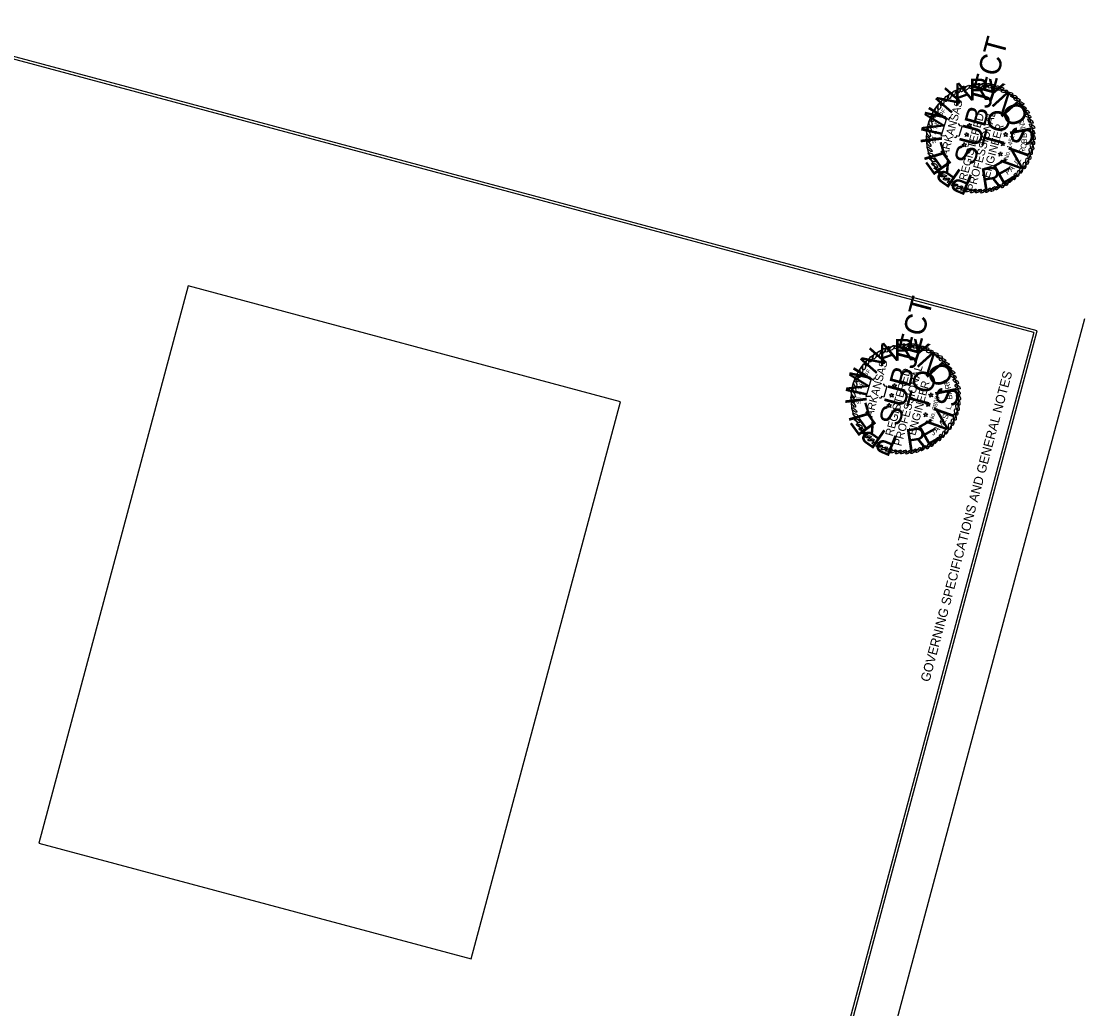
# Model space of a CAD drawing. Extents: x 1272249 to 1274802, y 195141 to 198564.
# Drawn here: x 1273878 to 1274802, y 197678 to 198536 of the extents above; entities that cross this region are included whole.
import ezdxf

# ---------------------------------------------------------------- set-up
doc = ezdxf.new("R2010")
doc.units = 0
for name, color, linetype in [('Level 61', 7, 'Continuous'), ('R_Border', 7, 'Continuous'), ('R_Border Notes', 7, 'Continuous'), ('R_Border PE', 7, 'Continuous'), ('R_Border Prem', 7, 'Continuous'), ('R_No Plot', 7, 'Continuous'), ('T_Drafting', 7, 'Continuous'), ('TXT', 7, 'Continuous')]:
    doc.layers.add(name, color=color, linetype=linetype)

msp = doc.modelspace()

# ---------------------------------------------------------------- linework, layer by layer
at = {"layer": 'Level 61'}
for points in [[(1274681.2, 198436.47), (1274677.79, 198436.3), (1274682.45, 198451.93), (1274684.26, 198450.2), (1274685.05, 198452.58), (1274685.3, 198452.35)], [(1274692.52, 198447.21), (1274693.57, 198445.53), (1274695.82, 198445.24), (1274693.01, 198435.9), (1274690.98, 198436.44), (1274690.53, 198434.75), (1274689.27, 198435.09)]]:
    msp.add_lwpolyline(points, dxfattribs=at)
for points in [[(1274700.33, 198446.05), (1274701.85, 198446.11), (1274702.23, 198447.51), (1274702.65, 198446.2), (1274704.22, 198446.25), (1274703.04, 198445.32), (1274703.6, 198443.93), (1274702.26, 198444.76), (1274701.23, 198443.79), (1274701.62, 198445.24)], [(1274698, 198437.93), (1274699.37, 198438.02), (1274699.72, 198439.33), (1274700.32, 198438.08), (1274701.74, 198438.17), (1274700.71, 198437.2), (1274701.12, 198435.85), (1274699.93, 198436.63), (1274698.77, 198435.75), (1274699.14, 198437.15)], [(1274731.75, 198438.1), (1274733.31, 198438.14), (1274733.69, 198439.55), (1274734.07, 198438.25), (1274735.62, 198438.25), (1274734.45, 198437.37), (1274735.01, 198435.98), (1274733.68, 198436.8), (1274732.69, 198435.83), (1274733.08, 198437.28)], [(1274695.78, 198429.05), (1274697.3, 198429.11), (1274697.67, 198430.51), (1274698.08, 198429.16), (1274699.65, 198429.2), (1274698.48, 198428.32), (1274699.04, 198426.93), (1274697.71, 198427.76), (1274696.67, 198426.79), (1274697.06, 198428.24)], [(1274729.41, 198429.97), (1274730.84, 198430.06), (1274731.18, 198431.36), (1274731.69, 198429.98), (1274733.15, 198430.22), (1274732.12, 198429.25), (1274732.53, 198427.9), (1274731.35, 198428.68), (1274730.23, 198427.79), (1274730.6, 198429.19)], [(1274727.19, 198421.1), (1274728.74, 198421.1), (1274729.13, 198422.54), (1274729.5, 198421.2), (1274731.06, 198421.25), (1274729.9, 198420.37), (1274730.45, 198418.98), (1274729.12, 198419.8), (1274728.14, 198418.83), (1274728.52, 198420.27)]]:
    msp.add_lwpolyline(points, close=True, dxfattribs=at)
for centre, major_axis, ratio in [((1274708.96, 198480.11), (-2.37, -1.59), 0.40589), ((1274713.08, 198480.37), (-2.37, -1.59), 0.40589), ((1274717.01, 198480.21), (-2.44, -1.47), 0.40589), ((1274685.3, 198471.19), (-0.68, -2.34), 0.475469), ((1274688.59, 198473.22), (-0.99, -2.37), 0.451028), ((1274692.46, 198475.45), (-1.24, -2.35), 0.436264), ((1274696.21, 198477.13), (-1.45, -2.35), 0.418512), ((1274700.23, 198478.26), (-1.98, -2.05), 0.40589), ((1274704.71, 198479.65), (-2.19, -1.83), 0.40589), ((1274721.14, 198479.55), (-2.63, -1.11), 0.40589), ((1274725.16, 198478.56), (-2.77, -0.69), 0.40589), ((1274729.21, 198477.21), (-2.82, -0.44), 0.40589), ((1274732.73, 198475.22), (-2.85, 0), 0.40589), ((1274737.09, 198473.12), (-2.84, 0.23), 0.40589), ((1274676.07, 198461.88), (-0.19, -2.43), 0.475469), ((1274678.8, 198465.21), (-0.42, -2.4), 0.475469), ((1274681.96, 198468.67), (-0.42, -2.4), 0.475469), ((1274740.89, 198470.66), (-2.79, 0.58), 0.40589), ((1274743.69, 198467.96), (-2.79, 0.58), 0.40589), ((1274746.77, 198464.8), (-2.72, 0.87), 0.40589), ((1274671.74, 198455.06), (0.64, -2.35), 0.475469), ((1274673.72, 198458.65), (0.11, -2.43), 0.475469), ((1274749.02, 198461.27), (-2.6, 1.17), 0.40589), ((1274751.71, 198457.69), (-2.6, 1.17), 0.40589), ((1274753.15, 198453.72), (-2.5, 1.37), 0.40589), ((1274668.43, 198447.24), (0.64, -2.35), 0.475469), ((1274669.98, 198451.33), (0.64, -2.35), 0.475469), ((1274755.29, 198449.34), (-2.24, 1.77), 0.40589), ((1274756.72, 198444.8), (-2.18, 1.84), 0.40589), ((1274666.48, 198433.9), (1.65, -2.32), 0.329518), ((1274666.74, 198438.36), (1.44, -2.76), 0.348728), ((1274667.57, 198442.46), (0.96, -2.26), 0.44237), ((1274756.97, 198440.39), (-1.78, 2.23), 0.40589), ((1274757.66, 198435.72), (-1.39, 2.49), 0.40589), ((1274666.85, 198429.59), (1.68, -2.3), 0.329518), ((1274667.6, 198424.74), (2.17, -1.85), 0.329518), ((1274756.63, 198426.91), (-1.01, 2.67), 0.40589), ((1274757.22, 198431.45), (-1.21, 2.58), 0.40589), ((1274668.88, 198420.07), (2.46, -1.45), 0.375751), ((1274670.04, 198415.66), (2.46, -1.45), 0.394697), ((1274754.3, 198418.6), (-0.77, 2.75), 0.40589), ((1274755.55, 198423.01), (-0.77, 2.75), 0.40589), ((1274672.05, 198411.02), (2.46, -1.45), 0.391724), ((1274674.33, 198407.74), (2.75, -0.74), 0.322879), ((1274747.27, 198406.74), (0.51, 2.81), 0.40589), ((1274750.09, 198410.64), (-0.03, 2.85), 0.40589), ((1274752.44, 198414.31), (-0.03, 2.85), 0.40589), ((1274676.62, 198404.65), (2.75, -0.74), 0.322879), ((1274679.54, 198401.59), (2.85, 0.05), 0.322879), ((1274682.27, 198398.91), (2.85, 0.05), 0.322879), ((1274738.4, 198398.43), (1.3, 2.54), 0.322879), ((1274741.77, 198401.05), (0.51, 2.81), 0.322879), ((1274744.52, 198403.77), (0.51, 2.81), 0.322879), ((1274685.65, 198396.18), (2.85, 0.05), 0.322879), ((1274689.13, 198393.62), (2.85, 0.05), 0.322879), ((1274693.48, 198391.62), (2.73, 0.84), 0.322879), ((1274697.3, 198390.33), (2.73, 0.84), 0.322879), ((1274701.31, 198389), (2.73, 0.84), 0.322879), ((1274705.68, 198388.55), (2.51, 1.36), 0.322879), ((1274709.93, 198388.39), (2.51, 1.36), 0.322879), ((1274714.53, 198388.47), (2.37, 1.59), 0.322879), ((1274718.6, 198389.11), (2.18, 1.83), 0.322879), ((1274722.85, 198390.16), (1.87, 2.16), 0.322879), ((1274727.06, 198391.77), (1.87, 2.16), 0.322879), ((1274731.53, 198393.7), (1.3, 2.54), 0.322879), ((1274735.06, 198395.68), (1.3, 2.54), 0.322879)]:
    msp.add_ellipse(centre, major_axis=major_axis, ratio=ratio, dxfattribs=at)
at = {"layer": 'R_Border'}
for p, q in [((1274758.15, 198265.52), (1273758.4, 198533.37)), ((1274343.59, 196564.79), (1274802.45, 198277.69)), ((1274758.15, 198265.52), (1274345.89, 196726.94))]:
    msp.add_line(p, q, dxfattribs=at)
at = {"layer": 'R_Border PE'}
for points in [[(1274615.82, 198209.95), (1274612.38, 198209.77), (1274617.07, 198225.52), (1274618.9, 198223.78), (1274619.69, 198226.17), (1274619.95, 198225.95)], [(1274627.22, 198220.76), (1274628.27, 198219.07), (1274630.54, 198218.78), (1274627.71, 198209.37), (1274625.66, 198209.92), (1274625.21, 198208.21), (1274623.94, 198208.55)]]:
    msp.add_lwpolyline(points, dxfattribs=at)
for points in [[(1274635.09, 198219.59), (1274636.62, 198219.65), (1274637, 198221.06), (1274637.43, 198219.75), (1274639, 198219.8), (1274637.81, 198218.86), (1274638.38, 198217.46), (1274637.03, 198218.29), (1274635.99, 198217.32), (1274636.38, 198218.78)], [(1274632.74, 198211.41), (1274634.12, 198211.51), (1274634.47, 198212.82), (1274635.08, 198211.57), (1274636.51, 198211.65), (1274635.46, 198210.68), (1274635.88, 198209.32), (1274634.69, 198210.11), (1274633.51, 198209.22), (1274633.89, 198210.63)], [(1274664.39, 198203.4), (1274665.82, 198203.48), (1274666.17, 198204.8), (1274666.69, 198203.41), (1274668.16, 198203.64), (1274667.11, 198202.67), (1274667.53, 198201.31), (1274666.33, 198202.1), (1274665.21, 198201.2), (1274665.58, 198202.61)], [(1274666.74, 198211.58), (1274668.31, 198211.63), (1274668.69, 198213.04), (1274669.07, 198211.74), (1274670.64, 198211.74), (1274669.46, 198210.85), (1274670.03, 198209.45), (1274668.68, 198210.28), (1274667.69, 198209.29), (1274668.08, 198210.75)], [(1274630.5, 198202.47), (1274632.03, 198202.53), (1274632.41, 198203.94), (1274632.82, 198202.57), (1274634.4, 198202.62), (1274633.22, 198201.74), (1274633.79, 198200.33), (1274632.45, 198201.16), (1274631.4, 198200.19), (1274631.79, 198201.65)], [(1274662.15, 198194.46), (1274663.71, 198194.45), (1274664.1, 198195.91), (1274664.47, 198194.56), (1274666.05, 198194.61), (1274664.87, 198193.73), (1274665.44, 198192.32), (1274664.09, 198193.15), (1274663.1, 198192.17), (1274663.49, 198193.63)]]:
    msp.add_lwpolyline(points, close=True, dxfattribs=at)
for centre, major_axis, ratio in [((1274627.16, 198249.2), (-1.25, -2.36), 0.436264), ((1274630.93, 198250.9), (-1.46, -2.37), 0.418512), ((1274634.99, 198252.03), (-2, -2.07), 0.40589), ((1274639.49, 198253.44), (-2.21, -1.84), 0.40589), ((1274643.78, 198253.9), (-2.38, -1.6), 0.40589), ((1274647.93, 198254.17), (-2.38, -1.6), 0.40589), ((1274651.89, 198254), (-2.46, -1.48), 0.40589), ((1274656.05, 198253.33), (-2.65, -1.12), 0.40589), ((1274660.1, 198252.33), (-2.79, -0.7), 0.40589), ((1274664.18, 198250.97), (-2.84, -0.44), 0.40589), ((1274616.58, 198242.37), (-0.43, -2.42), 0.475469), ((1274619.94, 198244.91), (-0.69, -2.35), 0.475469), ((1274623.26, 198246.96), (-1, -2.38), 0.451028), ((1274667.73, 198248.97), (-2.87, 0), 0.40589), ((1274672.12, 198246.86), (-2.86, 0.24), 0.40589), ((1274675.95, 198244.38), (-2.81, 0.58), 0.40589), ((1274678.77, 198241.66), (-2.81, 0.58), 0.40589), ((1274608.27, 198232.28), (0.11, -2.45), 0.475469), ((1274610.64, 198235.53), (-0.19, -2.45), 0.475469), ((1274613.4, 198238.89), (-0.43, -2.42), 0.475469), ((1274681.88, 198238.48), (-2.74, 0.87), 0.40589), ((1274684.14, 198234.92), (-2.62, 1.18), 0.40589), ((1274686.85, 198231.31), (-2.62, 1.18), 0.40589), ((1274602.95, 198220.79), (0.65, -2.37), 0.475469), ((1274604.51, 198224.91), (0.65, -2.37), 0.475469), ((1274606.28, 198228.67), (0.65, -2.37), 0.475469), ((1274688.3, 198227.32), (-2.52, 1.38), 0.40589), ((1274690.46, 198222.9), (-2.25, 1.78), 0.40589), ((1274601.24, 198211.83), (1.45, -2.78), 0.348728), ((1274602.08, 198215.97), (0.97, -2.28), 0.44237), ((1274691.9, 198218.33), (-2.2, 1.85), 0.40589), ((1274692.15, 198213.88), (-1.79, 2.25), 0.40589), ((1274600.98, 198207.35), (1.66, -2.34), 0.329518), ((1274601.35, 198203), (1.69, -2.32), 0.329518), ((1274692.4, 198204.88), (-1.22, 2.6), 0.40589), ((1274692.84, 198209.18), (-1.41, 2.51), 0.40589), ((1274602.11, 198198.11), (2.18, -1.87), 0.329518), ((1274690.72, 198196.38), (-0.77, 2.77), 0.40589), ((1274691.81, 198200.31), (-1.02, 2.69), 0.40589), ((1274603.4, 198193.41), (2.47, -1.46), 0.375751), ((1274604.57, 198188.96), (2.47, -1.46), 0.394697), ((1274606.6, 198184.29), (2.47, -1.46), 0.391724), ((1274685.22, 198183.91), (-0.03, 2.87), 0.40589), ((1274687.59, 198187.6), (-0.03, 2.87), 0.40589), ((1274689.46, 198191.92), (-0.77, 2.77), 0.40589), ((1274608.89, 198180.99), (2.78, -0.75), 0.322879), ((1274611.2, 198177.87), (2.78, -0.75), 0.322879), ((1274676.84, 198174.25), (0.51, 2.83), 0.322879), ((1274679.61, 198176.99), (0.51, 2.83), 0.322879), ((1274682.38, 198179.98), (0.51, 2.83), 0.40589), ((1274614.14, 198174.8), (2.87, 0.05), 0.322879), ((1274616.89, 198172.09), (2.87, 0.05), 0.322879), ((1274620.29, 198169.34), (2.87, 0.05), 0.322879), ((1274623.8, 198166.76), (2.87, 0.05), 0.322879), ((1274666.52, 198166.84), (1.31, 2.56), 0.322879), ((1274670.07, 198168.84), (1.31, 2.56), 0.322879), ((1274673.44, 198171.61), (1.31, 2.56), 0.322879), ((1274628.18, 198164.75), (2.75, 0.85), 0.322879), ((1274632.03, 198163.45), (2.75, 0.85), 0.322879), ((1274636.07, 198162.11), (2.75, 0.85), 0.322879), ((1274640.47, 198161.65), (2.53, 1.37), 0.322879), ((1274644.76, 198161.49), (2.53, 1.37), 0.322879), ((1274649.39, 198161.58), (2.39, 1.6), 0.322879), ((1274653.49, 198162.22), (2.2, 1.85), 0.322879), ((1274657.78, 198163.28), (1.88, 2.17), 0.322879), ((1274662.02, 198164.89), (1.88, 2.17), 0.322879)]:
    msp.add_ellipse(centre, major_axis=major_axis, ratio=ratio, dxfattribs=at)
at = {"layer": 'R_Border Prem'}
msp.add_circle((1274646.08, 198208.21), 46.64, dxfattribs=at)
at = {"layer": 'R_No Plot'}
msp.add_lwpolyline([(1274347.9, 196724.34), (1274761.15, 198266.78), (1273756.3, 198536.04), (1273343.08, 196993.49)], close=True, dxfattribs=at)
at = {"layer": 'T_Drafting'}
msp.add_lwpolyline([(1274269.04, 197720.83), (1274398.85, 198205.3), (1274023.05, 198305.99), (1273893.24, 197821.53)], close=True, dxfattribs=at)
at = {"layer": 'TXT'}
msp.add_circle((1274711.24, 198434.75), 46.29, dxfattribs=at)

# ---------------------------------------------------------------- texts
at = {"layer": 'Level 61'}
for s, height, rotation, p in [('ARKANSAS', 6.907, 75, (1274683.43, 198417.92)), ('O', 3.45, 57.62207, (1274678.03, 198452.65)), ('F', 3.45, 53.00216, (1274680.19, 198456.05)), (' REGISTERED', 6.9069, 75, (1274698.91, 198394.59)), (' PROFESSIONAL', 6.9069, 75, (1274706.13, 198385.19)), ('T', 3.45, 76.10172, (1274673.99, 198441.62)), ('E', 3.45, 71.48181, (1274675.02, 198445.48)), (' ENGINEER', 6.907, 75, (1274718.96, 198396.73)), ('S', 4.8, 110.22192, (1274749.96, 198447.78)), ('N', 4.8, 104.62152, (1274751.26, 198443.32)), ('T', 3.45, 89.96145, (1274673.12, 198433.72)), ('A', 3.45, 80.72162, (1274673.2, 198437.53)), ('No. 14517', 3.946, 75, (1274735.7, 198415.19)), ('I', 4.8, 100.84873, (1274751.8, 198440.23)), ('B', 4.8, 89.97753, (1274752.24, 198434.65)), ('S', 3.45, 94.58136, (1274673.32, 198429.84)), ('O', 4.8, 77.18851, (1274751.07, 198424.75)), ('B', 4.8, 83.75712, (1274751.98, 198429.62)), ('R', 4.8, 70.56746, (1274749.52, 198420.47)), ('A', 4.8, 43.01709, (1274738.7, 198404.92)), ('U', 4.8, 48.61749, (1274742.27, 198408.51)), ('L', 4.8, 59.8183, (1274745.69, 198412.68)), ('P', 4.8, 37.41669, (1274735.29, 198402.21))]:
    msp.add_text(s, height=height, rotation=rotation, dxfattribs=at).set_placement(p)
at = {"layer": 'R_Border Notes'}
msp.add_text('GOVERNING SPECIFICATIONS AND GENERAL NOTES', height=8.06, rotation=75.00018, dxfattribs=at).set_placement((1274667.36, 197961.19))
at = {"layer": 'R_Border PE'}
for s, height, rotation, p in [('ARKANSAS', 6.959, 75, (1274618.06, 198191.25)), ('F', 3.48, 53.00216, (1274614.79, 198229.67)), ('REGISTERED', 6.959, 75, (1274635.56, 198174.83)), ('PROFESSIONAL', 6.9587, 75, (1274643, 198166.21)), ('O', 3.48, 57.62207, (1274612.62, 198226.24)), ('ENGINEER', 6.959, 75, (1274655.18, 198175.46)), ('R', 4.84, 110.22192, (1274685.1, 198221.32)), ('A', 3.48, 80.72162, (1274607.76, 198211.01)), ('T', 3.48, 76.10172, (1274608.55, 198215.13)), ('E', 3.48, 71.48181, (1274609.59, 198219.02)), ('R', 4.84, 104.62152, (1274686.4, 198216.85)), ('A', 4.84, 99.02112, (1274687.2, 198212.05)), ('S', 3.48, 94.58136, (1274607.87, 198203.26)), ('T', 3.48, 89.96145, (1274607.67, 198207.18)), ('No. 9808', 3.976, 75, (1274670.57, 198187.92)), ('B', 4.84, 93.42071, (1274687.37, 198207.41)), ('L', 4.84, 76.61951, (1274685.96, 198198.09)), ('.', 4.84, 82.21991, (1274686.83, 198202.5)), ('M', 4.84, 48.61749, (1274677.16, 198181.57)), ('E', 4.84, 59.8183, (1274680.39, 198185.66)), ('S', 4.84, 65.4187, (1274682.65, 198189.43)), ('J', 4.84, 37.41669, (1274670.56, 198175.62)), ('A', 4.84, 43.01709, (1274673.74, 198178.16))]:
    msp.add_text(s, height=height, rotation=rotation, dxfattribs=at).set_placement(p)
at = {"layer": 'R_Border Prem'}
for s, rotation, p in [('SUBJECT', 75, (1274641.32, 198183.09)), ('Y', 341.11312, (1274647.27, 198242.67)), ('N', 48.71994, (1274619.68, 198228.05)), ('A', 19.74559, (1274625.17, 198235.71)), ('R', 0.42935, (1274636.42, 198241.09)), ('N', 132.13775, (1274681.22, 198237.22)), ('I', 58.37806, (1274615.58, 198221.53)), ('O', 111.57544, (1274689.06, 198223.28)), ('M', 77.69429, (1274612.45, 198208.66)), ('TO', 75, (1274665.25, 198196.29)), ('I', 101.29428, (1274691.61, 198212.74)), ('S', 80.73197, (1274690.83, 198199.91)), ('I', 97.01053, (1274613.38, 198204.18)), ('L', 106.66865, (1274616.51, 198192.08)), ('E', 125.98488, (1274622.37, 198184.77)), ('V', 49.8885, (1274677.72, 198175.11)), ('I', 70.45081, (1274687.74, 198189.53)), ('R', 145.30112, (1274630.94, 198178.62)), ('E', 29.32618, (1274664.83, 198166.51)), ('R', 8.76387, (1274648.54, 198162.53)), ('P', 157.60888, (1274641.17, 198174.57))]:
    msp.add_text(s, height=18.76, rotation=rotation, dxfattribs=at).set_placement(p)
at = {"layer": 'TXT'}
for s, rotation, p in [('SUBJECT', 75, (1274706.49, 198409.8)), ('A', 19.74559, (1274690.49, 198462.04)), ('R', 0.42935, (1274701.65, 198467.39)), ('Y', 341.11312, (1274712.42, 198468.95)), ('N', 48.71994, (1274685.04, 198454.44)), ('N', 132.13775, (1274746.12, 198463.54)), ('O', 111.57544, (1274753.91, 198449.71)), ('M', 77.69429, (1274677.86, 198435.2)), ('I', 58.37806, (1274680.97, 198447.98)), ('TO', 75, (1274730.26, 198422.9)), ('I', 101.29428, (1274756.44, 198439.25)), ('S', 80.73197, (1274755.66, 198426.51)), ('I', 97.01053, (1274678.79, 198430.75)), ('L', 106.66865, (1274681.89, 198418.74)), ('I', 70.45081, (1274752.59, 198416.21)), ('E', 125.98488, (1274687.71, 198411.49)), ('V', 49.8885, (1274742.65, 198401.89)), ('R', 145.30112, (1274696.22, 198405.38)), ('R', 8.76387, (1274713.68, 198389.41)), ('E', 29.32618, (1274729.85, 198393.36)), ('P', 157.60888, (1274706.37, 198401.36))]:
    msp.add_text(s, height=18.62, rotation=rotation, dxfattribs=at).set_placement(p)

doc.saveas('drawing.dxf')
